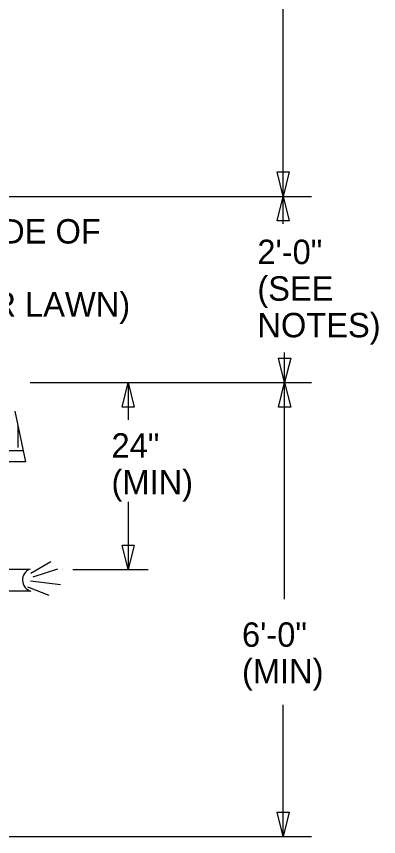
# Model space of a CAD drawing. Extents: x 10117 to 10169, y 10050 to 10161.
# Drawn here: x 10158.87 to 10168.77, y 10075.41 to 10097.81 of the extents above; entities that cross this region are included whole.
import ezdxf

# ---------------------------------------------------------------- set-up
doc = ezdxf.new("R2010")
doc.units = 0
for name, color, linetype in [('G-ANNO-TEXT', 7, 'Continuous'), ('G-DETL-LINE', 7, 'Continuous'), ('G-DETL-OTLN', 7, 'Continuous'), ('G-DETL-PATT', 7, 'Continuous')]:
    doc.layers.add(name, color=color, linetype=linetype)

msp = doc.modelspace()

# ---------------------------------------------------------------- linework, layer by layer
at = {"layer": 'G-ANNO-TEXT'}
for p, q in [((10166.163, 10092.896), (10166.163, 10111.47)), ((10149.402, 10092.896), (10166.935, 10092.896)), ((10166.162, 10092.147), (10166.162, 10092.896)), ((10166.202, 10087.81), (10166.202, 10088.629)), ((10159.25, 10087.81), (10166.935, 10087.81)), ((10161.928, 10087.81), (10161.928, 10086.793)), ((10166.202, 10081.896), (10166.202, 10087.81)), ((10161.928, 10084.551), (10161.928, 10082.704)), ((10160.42, 10082.704), (10162.472, 10082.704)), ((10166.163, 10075.412), (10166.163, 10079.012)), ((10150.068, 10075.412), (10166.935, 10075.412))]:
    msp.add_line(p, q, dxfattribs=at)
for points in [[(10166.329, 10093.563), (10166.163, 10092.896), (10165.996, 10093.563)], [(10165.996, 10092.229), (10166.163, 10092.896), (10166.329, 10092.229)], [(10166.369, 10088.476), (10166.202, 10087.81), (10166.036, 10088.476)], [(10161.761, 10087.143), (10161.928, 10087.81), (10162.094, 10087.143)], [(10166.036, 10087.143), (10166.202, 10087.81), (10166.369, 10087.143)], [(10162.094, 10083.371), (10161.928, 10082.704), (10161.761, 10083.371)], [(10166.329, 10076.078), (10166.163, 10075.412), (10165.996, 10076.078)]]:
    msp.add_lwpolyline(points, close=True, dxfattribs=at)
at = {"layer": 'G-DETL-LINE'}
for p, q in [((10158.827, 10087.027), (10159.127, 10085.647)), ((10159.127, 10085.647), (10148.946, 10085.652)), ((10159.27, 10082.606), (10159.819, 10082.925)), ((10159.33, 10082.506), (10160.009, 10082.726)), ((10159.181, 10082.237), (10159.759, 10082.007)), ((10159.26, 10082.396), (10160.078, 10082.296))]:
    msp.add_line(p, q, dxfattribs=at)
at = {"layer": 'G-DETL-OTLN'}
for p, q in [((10148.584, 10082.719), (10159.221, 10082.719)), ((10148.584, 10082.127), (10159.253, 10082.127))]:
    msp.add_line(p, q, dxfattribs=at)
msp.add_arc((10159.355, 10082.419), 0.314, 109.387, 254.428, dxfattribs=at)
at = {"layer": 'G-DETL-PATT'}
for p, q in [((10158.912, 10086.636), (10158.912, 10086.035)), ((10158.472, 10085.954), (10159.061, 10085.954))]:
    msp.add_line(p, q, dxfattribs=at)

# ---------------------------------------------------------------- texts
at = {"layer": 'G-ANNO-TEXT'}
for s, height, p in [('FINISHED GRADE OF ', 0.66667, (10152.116, 10091.608)), ('2\'-0" ', 0.6667, (10165.459, 10091.047)), ('(SEE ', 0.6667, (10165.459, 10090.047)), ('(PAVEMENT OR LAWN)', 0.66667, (10152.077, 10089.614)), ('NOTES)', 0.6667, (10165.459, 10089.047)), ('24"', 0.6667, (10161.473, 10085.76)), ('(MIN)', 0.6667, (10161.473, 10084.76)), ('6\'-0" ', 0.6667, (10165.039, 10080.595)), ('(MIN)', 0.6667, (10165.039, 10079.595))]:
    msp.add_text(s, height=height, dxfattribs=at).set_placement(p)

doc.saveas('drawing.dxf')
